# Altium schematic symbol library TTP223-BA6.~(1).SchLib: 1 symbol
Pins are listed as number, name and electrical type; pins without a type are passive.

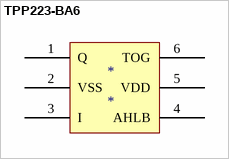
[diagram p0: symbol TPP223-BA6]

## TPP223-BA6
designator *
pins: 1 Q, 2 VSS, 3 I, 4 AHLB, 5 VDD, 6 TOG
